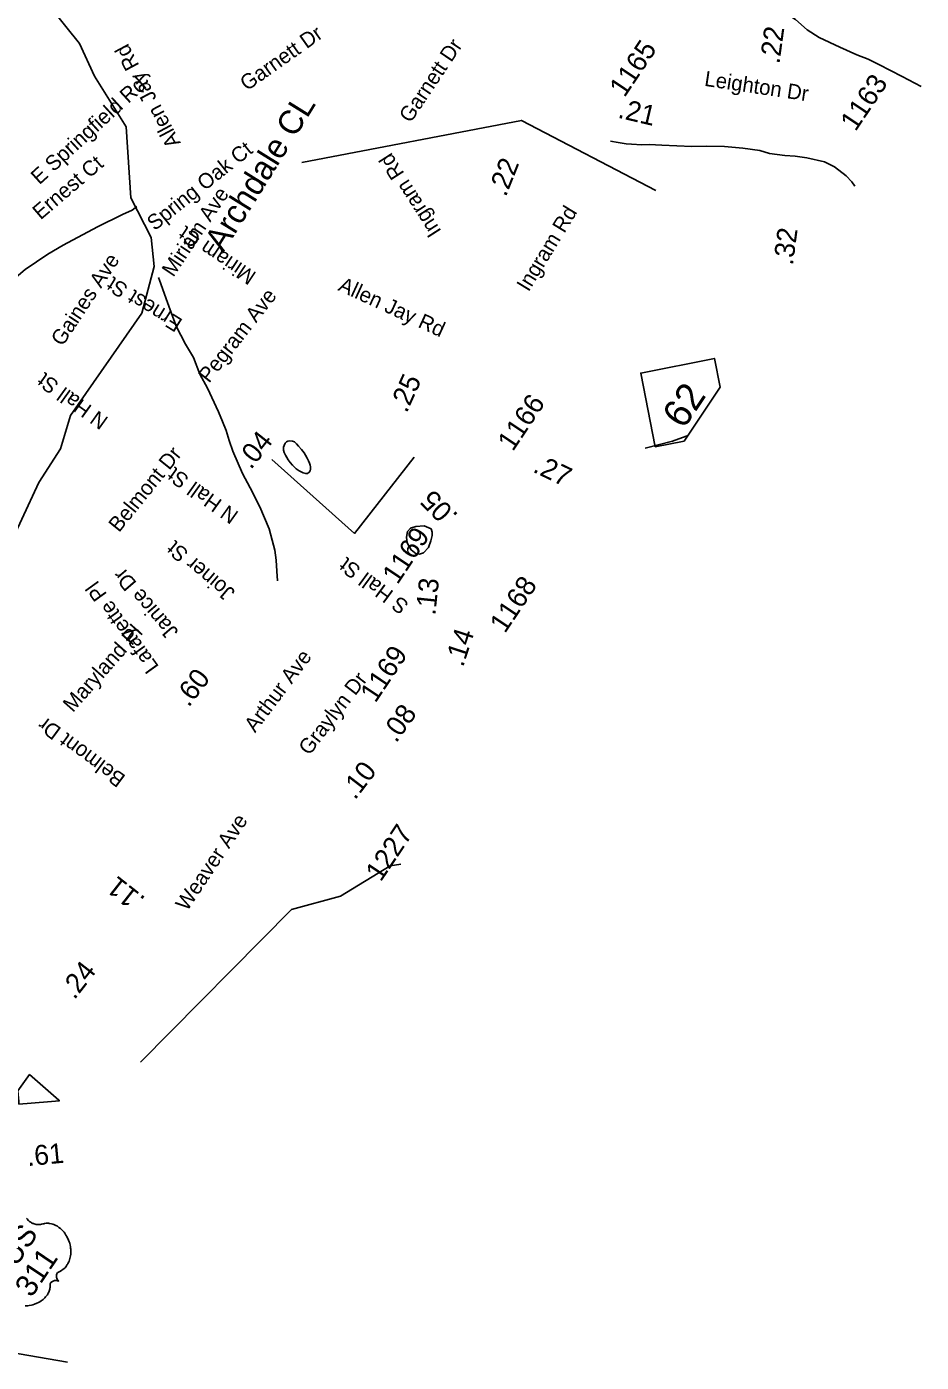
# Model space of a CAD drawing. Extents: x 1716282 to 1717158, y 799307 to 801078.
# Drawn here: x 1716771.4 to 1716852.8, y 799339.2 to 799460.6 of the extents above; entities that cross this region are included whole.
import ezdxf

# ---------------------------------------------------------------- set-up
doc = ezdxf.new("R2010")
doc.units = 0
for name, color, linetype in [('Exist Boundary Political City Limit New Hole', 7, 'Continuous'), ('Exist Civil Demographics Community Label', 7, 'Continuous'), ('Exist Hydrographic Misc Water Feature', 7, 'Continuous'), ('Exist Road Non-System Type 51 Label', 7, 'Continuous'), ('Exist Road Primary NC Mileage Hundredths English Label', 7, 'Continuous'), ('Exist Road Primary NC Service Mileage Hundredths English Label', 7, 'Continuous'), ('Exist Road Primary NC Shield CELL', 7, 'Continuous'), ('Exist Road Primary NC Shield Number Label', 7, 'Continuous'), ('Exist Road Primary US Mileage Hundredths English Label', 7, 'Continuous'), ('Exist Road Primary US Shield CELL', 7, 'Continuous'), ('Exist Road Primary US Shield Number Label', 7, 'Continuous'), ('Exist Road Secondary Mileage Hundredths English Label', 7, 'Continuous'), ('Exist Road Secondary Mileage Tenths English Label', 7, 'Continuous'), ('Exist Road Secondary Type 51 Number Label', 7, 'Continuous')]:
    doc.layers.add(name, color=color, linetype=linetype)

msp = doc.modelspace()

# ---------------------------------------------------------------- linework, layer by layer
at = {"layer": 'Exist Boundary Political City Limit New Hole'}
msp.add_lwpolyline([(1716773.3, 799362.86), (1716774.39, 799362.95), (1716774.32, 799363.01), (1716774.35, 799363.02), (1716771.68, 799365.33), (1716770.61, 799363.86), (1716770.69, 799362.9), (1716770.71, 799362.72), (1716770.71, 799362.65), (1716773.3, 799362.86)], dxfattribs=at)
at = {"layer": 'Exist Civil Demographics Community Label'}
msp.add_lwpolyline([(1716828.63, 799445.74), (1716816.41, 799452.12), (1716796.45, 799448.3)], dxfattribs=at)
at = {"layer": 'Exist Hydrographic Misc Water Feature'}
for points in [[(1716769.43, 799412.52), (1716772.52, 799419.19), (1716774.48, 799422.24), (1716775.39, 799425.28), (1716781.89, 799434.58), (1716783, 799438.82), (1716782.75, 799441.46), (1716780.88, 799445.09), (1716780.45, 799451.53), (1716777.57, 799456.13), (1716776.22, 799459.11), (1716773.61, 799462.35), (1716768.36, 799466.22)], [(1716852.78, 799455.19), (1716851.04, 799456.11), (1716848.91, 799457.21), (1716847.94, 799457.7), (1716846.91, 799458.09), (1716845.38, 799458.78), (1716843.48, 799459.65), (1716842.41, 799460.35), (1716841.34, 799461.29), (1716840.05, 799462.14), (1716839.29, 799462.62), (1716838.65, 799462.96), (1716838.28, 799463.14)], [(1716846.73, 799446.14), (1716846.47, 799446.54), (1716845.96, 799447.07), (1716844.88, 799447.91), (1716843.98, 799448.35), (1716842.37, 799448.72), (1716841.32, 799448.87), (1716840.37, 799448.92), (1716838.98, 799449.1), (1716838.09, 799449.39), (1716836.55, 799449.6), (1716834.88, 799449.73), (1716833.26, 799449.78), (1716831.91, 799449.75), (1716829.19, 799449.88), (1716828.02, 799449.92), (1716827.37, 799449.9), (1716826.42, 799449.95), (1716825.93, 799450), (1716825.2, 799450.11), (1716824.51, 799450.24)], [(1716781.42, 799444.3), (1716781.01, 799443.94), (1716780.12, 799443.57), (1716777.85, 799442.45), (1716774.72, 799440.76), (1716773.33, 799439.95), (1716771.29, 799438.57), (1716770.46, 799437.87), (1716769.55, 799436.84), (1716768.82, 799436.08), (1716768.29, 799435.77), (1716767.62, 799435.77), (1716767.04, 799435.78), (1716764.6, 799436.43), (1716764.22, 799436.55)], [(1716783.39, 799437.82), (1716783.48, 799437.59), (1716784.21, 799435.57), (1716785.02, 799433.41), (1716785.87, 799431.77), (1716786.58, 799430.55), (1716787.16, 799429.03), (1716787.87, 799427.77), (1716788.86, 799425.62), (1716789.24, 799424.73), (1716789.56, 799423.91), (1716789.83, 799423.02), (1716790.18, 799422.04), (1716791.04, 799420.02), (1716791.73, 799418.7), (1716792.62, 799416.97), (1716793.48, 799414.98), (1716793.75, 799413.95), (1716793.99, 799413.02), (1716794.12, 799412.12), (1716794.16, 799411.11), (1716794.24, 799410.24)], [(1716831.56, 799423.47), (1716831.4, 799423.4), (1716830.17, 799422.94), (1716827.68, 799422.32)], [(1716797.05, 799421.15), (1716796.94, 799421.4), (1716796.77, 799421.66), (1716796.64, 799421.88), (1716796.42, 799422.18), (1716796.15, 799422.5), (1716795.97, 799422.7), (1716795.77, 799422.87), (1716795.58, 799422.96), (1716795.33, 799422.99), (1716795.17, 799422.96), (1716795.04, 799422.88), (1716794.93, 799422.77), (1716794.82, 799422.56), (1716794.77, 799422.39), (1716794.78, 799422.14), (1716794.84, 799421.92), (1716794.95, 799421.67), (1716795.13, 799421.37), (1716795.19, 799421.26), (1716795.38, 799421.02), (1716795.6, 799420.77), (1716795.76, 799420.59), (1716795.93, 799420.44), (1716796.2, 799420.26), (1716796.38, 799420.16), (1716796.56, 799420.07), (1716796.79, 799419.99), (1716796.89, 799419.99), (1716796.97, 799420.01), (1716797.12, 799420.12), (1716797.2, 799420.24), (1716797.24, 799420.39), (1716797.24, 799420.6), (1716797.21, 799420.76), (1716797.13, 799420.95), (1716797.05, 799421.15)], [(1716797.05, 799421.15), (1716796.94, 799421.4), (1716796.64, 799421.88), (1716796.42, 799422.18), (1716796.15, 799422.5), (1716795.97, 799422.7), (1716795.77, 799422.87), (1716795.58, 799422.96), (1716795.33, 799422.99), (1716795.17, 799422.96), (1716795.04, 799422.88), (1716794.93, 799422.77), (1716794.82, 799422.56), (1716794.77, 799422.39), (1716794.78, 799422.14), (1716794.84, 799421.92), (1716794.95, 799421.67), (1716795.19, 799421.26), (1716795.38, 799421.02), (1716795.6, 799420.77), (1716795.76, 799420.59), (1716795.93, 799420.44), (1716796.2, 799420.26), (1716796.38, 799420.16), (1716796.56, 799420.07), (1716796.79, 799419.99), (1716796.89, 799419.99), (1716796.97, 799420.01), (1716797.12, 799420.12), (1716797.2, 799420.24), (1716797.24, 799420.39), (1716797.24, 799420.6), (1716797.21, 799420.76), (1716797.13, 799420.95), (1716797.05, 799421.15)], [(1716808.19, 799414.98), (1716807.56, 799415.24), (1716806.82, 799415.18), (1716806.32, 799415.02), (1716806.05, 799414.72), (1716805.95, 799414.22), (1716806.01, 799413.69), (1716806.38, 799413.05), (1716806.84, 799412.7), (1716807.14, 799412.67), (1716807.5, 799412.78), (1716807.97, 799413.27), (1716808.17, 799413.87), (1716808.3, 799414.37), (1716808.29, 799414.67), (1716808.19, 799414.98)], [(1716808.19, 799414.98), (1716807.56, 799415.24), (1716806.82, 799415.18), (1716806.32, 799415.02), (1716806.05, 799414.72), (1716805.95, 799414.22), (1716806.01, 799413.69), (1716806.38, 799413.05), (1716806.84, 799412.7), (1716807.14, 799412.67), (1716807.5, 799412.78), (1716807.97, 799413.27), (1716808.17, 799413.87), (1716808.3, 799414.37), (1716808.29, 799414.67), (1716808.19, 799414.98)], [(1716805.46, 799384.48), (1716804.47, 799384.33), (1716799.97, 799381.55), (1716795.49, 799380.36), (1716781.76, 799366.47)], [(1716775.13, 799339.17), (1716768.07, 799340.4), (1716766.91, 799340.9)]]:
    msp.add_lwpolyline(points, dxfattribs=at)
at = {"layer": 'Exist Road Primary NC Shield CELL'}
msp.add_line((1716831.21, 799422.96), (1716834.48, 799427.85), dxfattribs=at)
msp.add_lwpolyline([(1716834.48, 799427.85), (1716833.97, 799430.47), (1716827.27, 799429.14), (1716828.59, 799422.44), (1716831.21, 799422.96)], dxfattribs=at)
at = {"layer": 'Exist Road Primary US Shield CELL'}
msp.add_lwpolyline([(1716771.4, 799352.28), (1716771.48, 799352.18), (1716771.53, 799352.11), (1716771.58, 799352.06), (1716771.68, 799351.97), (1716771.73, 799351.93), (1716771.79, 799351.9), (1716771.84, 799351.86), (1716771.9, 799351.83), (1716771.97, 799351.8), (1716772.02, 799351.78), (1716772.09, 799351.75), (1716772.18, 799351.73), (1716772.27, 799351.71), (1716772.42, 799351.69), (1716772.58, 799351.69), (1716772.68, 799351.7), (1716772.77, 799351.72), (1716772.89, 799351.76), (1716772.96, 799351.77), (1716773.04, 799351.79), (1716773.19, 799351.81), (1716773.25, 799351.81), (1716773.32, 799351.81), (1716773.39, 799351.81), (1716773.47, 799351.8), (1716773.53, 799351.79), (1716773.67, 799351.76), (1716773.8, 799351.73), (1716773.87, 799351.7), (1716774.01, 799351.64), (1716774.08, 799351.61), (1716774.21, 799351.54), (1716774.35, 799351.44), (1716774.49, 799351.33), (1716774.63, 799351.2), (1716774.72, 799351.11), (1716774.81, 799351), (1716774.89, 799350.9), (1716774.99, 799350.74), (1716775.07, 799350.62), (1716775.14, 799350.47), (1716775.19, 799350.38), (1716775.23, 799350.27), (1716775.28, 799350.14), (1716775.33, 799349.99), (1716775.37, 799349.83), (1716775.39, 799349.7), (1716775.41, 799349.54), (1716775.42, 799349.45), (1716775.43, 799349.32), (1716775.43, 799349.15), (1716775.42, 799348.99), (1716775.4, 799348.85), (1716775.38, 799348.74), (1716775.35, 799348.6), (1716775.28, 799348.37), (1716775.24, 799348.3), (1716775.2, 799348.21), (1716775.16, 799348.13), (1716775.11, 799348.05), (1716775.05, 799347.95), (1716774.97, 799347.85), (1716774.9, 799347.77), (1716774.81, 799347.69), (1716774.71, 799347.6), (1716774.61, 799347.54), (1716774.5, 799347.47), (1716774.3, 799347.38), (1716774.24, 799347.35), (1716774.22, 799347.33), (1716774.18, 799347.27), (1716774.15, 799347.21), (1716774.13, 799347.13), (1716774.13, 799347.08), (1716774.13, 799347.01), (1716774.13, 799346.96), (1716774.14, 799346.89), (1716774.16, 799346.83), (1716774.17, 799346.79), (1716774.21, 799346.7), (1716774.23, 799346.66), (1716774.27, 799346.62), (1716774.32, 799346.56), (1716774.23, 799346.59), (1716774.16, 799346.61), (1716774.09, 799346.61), (1716774.03, 799346.61), (1716773.95, 799346.6), (1716773.89, 799346.58), (1716773.82, 799346.56), (1716773.75, 799346.53), (1716773.7, 799346.5), (1716773.66, 799346.47), (1716773.62, 799346.44), (1716773.59, 799346.4), (1716773.57, 799346.37), (1716773.55, 799346.32), (1716773.56, 799346.23), (1716773.56, 799346.15), (1716773.55, 799346.07), (1716773.54, 799345.97), (1716773.53, 799345.9), (1716773.52, 799345.83), (1716773.49, 799345.74), (1716773.46, 799345.64), (1716773.42, 799345.55), (1716773.38, 799345.47), (1716773.34, 799345.39), (1716773.3, 799345.32), (1716773.25, 799345.25), (1716773.2, 799345.19), (1716773.14, 799345.11), (1716773.06, 799345.03), (1716772.99, 799344.96), (1716772.91, 799344.89), (1716772.82, 799344.82), (1716772.72, 799344.75), (1716772.6, 799344.67), (1716772.5, 799344.62), (1716772.34, 799344.54), (1716772.14, 799344.46), (1716771.97, 799344.41), (1716771.84, 799344.37), (1716771.63, 799344.33), (1716771.51, 799344.32), (1716771.29, 799344.3)], dxfattribs=at)
at = {"layer": 'Exist Road Secondary Mileage Hundredths English Label'}
msp.add_lwpolyline([(1716806.66, 799421.48), (1716801.23, 799414.55), (1716793.7, 799421.28)], dxfattribs=at)

# ---------------------------------------------------------------- texts
at = {"layer": 'Exist Civil Demographics Community Label'}
msp.add_text('Archdale CL', height=2.175, rotation=58.1089, dxfattribs=at).set_placement((1716789.31, 799440.03))
at = {"layer": 'Exist Road Non-System Type 51 Label'}
for s, height, rotation, p in [('Garnett Dr', 1.377, 35.2263, (1716791.44, 799454.75)), ('Allen Jay Rd', 1.3775, 118.0648, (1716785.45, 799450.07)), ('Garnett Dr', 1.377, 56.2051, (1716806.33, 799451.81)), ('Leighton Dr', 1.3775, 351.4609, (1716833, 799455.27)), ('E Springfield Rd', 1.3775, 42.4386, (1716772.57, 799446.21)), ('Spring Oak Ct', 1.3775, 38.5894, (1716783.05, 799442.03)), ('Ingram Rd', 1.377, 122.6768, (1716809.18, 799442.04)), ('Ernest Ct', 1.377, 40.5143, (1716772.68, 799443.02)), ('Miriam Ave', 1.377, 56.2051, (1716784.75, 799437.8)), ('Ingram Rd', 1.377, 58.5915, (1716817.06, 799436.46)), ('Miriam Ct', 1.377, 146.2051, (1716792.39, 799438.22)), ('Gaines Ave', 1.377, 56.5316, (1716774.67, 799431.5)), ('Ernest St', 1.377, 148.0612, (1716785.69, 799433.96)), ('Pegram Ave', 1.377, 52.0354, (1716788, 799428.16)), ('Allen Jay Rd', 1.3775, 335.3224, (1716799.66, 799436.69)), ('N Hall St', 1.377, 144.2745, (1716778.93, 799425.02)), ('Belmont Dr', 1.377, 51.0752, (1716779.81, 799414.58)), ('N Hall St', 1.378, 144.4699, (1716790.78, 799416.44)), ('Joiner St', 1.377, 139.9346, (1716790.46, 799409.31)), ('Janice Dr', 1.377, 130.6872, (1716785.29, 799405.64)), ('S Hall St', 1.377, 143.5924, (1716806.27, 799408.2)), ('Lafayette Pl', 1.3775, 125.6965, (1716783.49, 799402.44)), ('Maryland Pl', 1.3775, 48.5628, (1716775.61, 799398.21)), ('Arthur Ave', 1.377, 53.1039, (1716792.19, 799396.37)), ('Graylyn Dr', 1.377, 52.5196, (1716797.12, 799394.29)), ('Belmont Dr', 1.377, 143.5603, (1716780.5, 799392.47)), ('Weaver Ave', 1.377, 56.2051, (1716786, 799380.12))]:
    msp.add_text(s, height=height, rotation=rotation, dxfattribs=at).set_placement(p)
at = {"layer": 'Exist Road Primary NC Mileage Hundredths English Label'}
msp.add_text('.60', height=1.812, rotation=52.7783, dxfattribs=at).set_placement((1716786.15, 799398.68))
at = {"layer": 'Exist Road Primary NC Service Mileage Hundredths English Label'}
for s, height, rotation, p in [('.22', 1.812, 82.2733, (1716839.88, 799457.2)), ('.22', 1.813, 68.2476, (1716814.99, 799445.1)), ('.32', 1.812, 82.4242, (1716841.1, 799438.89)), ('.25', 1.812, 65.7217, (1716805.97, 799425.44))]:
    msp.add_text(s, height=height, rotation=rotation, dxfattribs=at).set_placement(p)
at = {"layer": 'Exist Road Primary NC Shield Number Label'}
msp.add_text('62', height=2.537, rotation=56.2051, dxfattribs=at).set_placement((1716831.18, 799423.97))
at = {"layer": 'Exist Road Primary US Mileage Hundredths English Label'}
msp.add_text('.61', height=1.813, rotation=5.3605, dxfattribs=at).set_placement((1716771.51, 799357.01))
at = {"layer": 'Exist Road Primary US Shield Number Label'}
for s, p in [('BUS', (1716769.47, 799346.3)), ('311', (1716771.86, 799344.98))]:
    msp.add_text(s, height=1.994, rotation=56.2051, dxfattribs=at).set_placement(p)
at = {"layer": 'Exist Road Secondary Mileage Hundredths English Label'}
for s, rotation, p in [('.04', 51.6948, (1716791.81, 799420.3)), ('.13', 84.079, (1716808.58, 799407.06)), ('.14', 71.9232, (1716811.1, 799402.33)), ('.08', 54.6538, (1716805.02, 799395.43)), ('.11', 141.824, (1716782.3, 799381.39)), ('.24', 52.1746, (1716775.76, 799372.08))]:
    msp.add_text(s, height=1.812, rotation=rotation, dxfattribs=at).set_placement(p)
at = {"layer": 'Exist Road Secondary Mileage Tenths English Label'}
for s, height, rotation, p in [('.21', 1.812, 346.7749, (1716825.11, 799452.38)), ('.27', 1.812, 334.4183, (1716817.37, 799420.19)), ('.05', 1.812, 134.465, (1716810.73, 799416.24)), ('.10', 1.813, 52.4866, (1716801.28, 799390.25))]:
    msp.add_text(s, height=height, rotation=rotation, dxfattribs=at).set_placement(p)
at = {"layer": 'Exist Road Secondary Type 51 Number Label'}
for s, p in [('1165', (1716825.79, 799454.14)), ('1163', (1716846.8, 799451.04)), ('1166', (1716815.63, 799421.94)), ('1169', (1716805.14, 799409.84)), ('1168', (1716814.91, 799405.39)), ('1169', (1716803.13, 799399.07)), ('1227', (1716803.62, 799382.8))]:
    msp.add_text(s, height=1.812, rotation=56.2051, dxfattribs=at).set_placement(p)

doc.saveas('drawing.dxf')
